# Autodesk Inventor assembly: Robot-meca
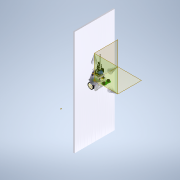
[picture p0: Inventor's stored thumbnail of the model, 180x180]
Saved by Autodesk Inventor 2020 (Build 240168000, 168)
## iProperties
Created: 2021-11
Part Number: Robot-meca
Document SubType Name: Assembly
Designer: bruno
Author: bruno
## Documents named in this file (5)
- C:\Users\bruno\OneDrive\Bureau\Robot-Inventor\Robot-equilibrage\Robot-meca.iam
- C:\Users\bruno\OneDrive\Bureau\Robot-Inventor\Robot-equilibrage\tapis.ipt
- C:\Users\bruno\OneDrive\Bureau\Robot-Inventor\Robot-equilibrage\Ensemble-base.iam
- C:\Users\bruno\OneDrive\Bureau\Robot-Inventor\Robot-equilibrage\Roulette.ipt
- C:\Users\bruno\OneDrive\Bureau\Robot-Inventor\Robot-equilibrage\roue.ipt
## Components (5 placed, 4 different names)
1. tapis:1 — Tangente:1, Tangente:2, Affleurement:1, Affleurement:2, Tangente:3
2. Ensemble-base:1 [sub-assembly] — Logement:2, Logement:3, Placage:1
3. Roulette:1 — Placage:1, Affleurement:2, Tangente:3
4. roue:1 — Logement:3, Tangente:2
5. roue:2 — Logement:2, Tangente:1, Affleurement:1
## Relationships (8: Tangent 3, Insert 2, Flush 2, Mate 1)
- Logement:2 [Insert]: Ensemble-base:1 ↔ roue:2
- Logement:3 [Insert]: Ensemble-base:1 ↔ roue:1
- Tangente:1: tapis:1 ↔ roue:2
- Tangente:2: tapis:1 ↔ roue:1
- Affleurement:1 [Flush]: tapis:1 ↔ roue:2
- Placage:1 [Mate]: Ensemble-base:1 ↔ Roulette:1
- Affleurement:2 [Flush]: tapis:1 ↔ Roulette:1
- Tangente:3: tapis:1 ↔ Roulette:1
